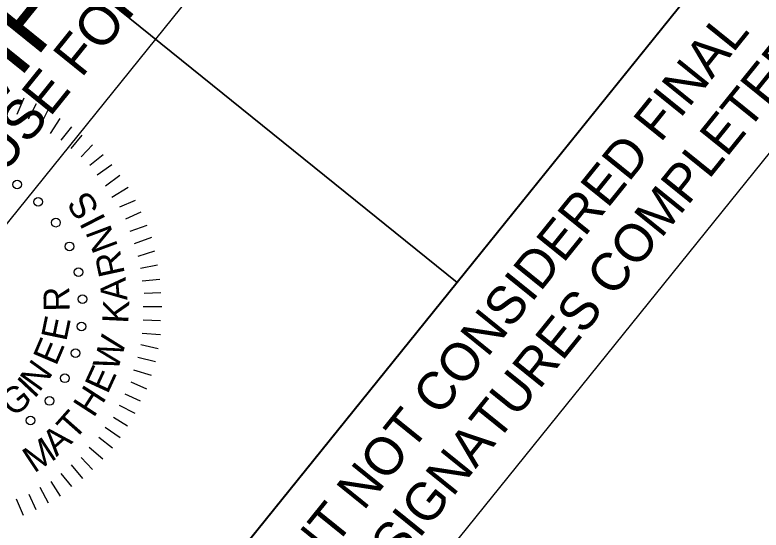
# Model space of a CAD drawing. Extents: x 1487832 to 1490056, y 498345 to 500343.
# Drawn here: x 1488928.7 to 1489037, y 500107.8 to 500182.6 of the extents above; entities that cross this region are included whole.
import ezdxf

# ---------------------------------------------------------------- set-up
doc = ezdxf.new("R2010")
doc.units = 0
for name, color, linetype in [('Old_Level_9', 7, 'Continuous'), ('Sheet Clip Boundary CELL', 7, 'Continuous'), ('Sheet Plan CELL', 7, 'Continuous'), ('Sheet Sticker Exception Certification CELL', 7, 'Continuous'), ('Sheet Sticker Incomplete CELL', 7, 'Continuous')]:
    doc.layers.add(name, color=color, linetype=linetype)

msp = doc.modelspace()

# ---------------------------------------------------------------- linework, layer by layer
at = {"layer": 'Old_Level_9'}
for p, q in [((1488930.01, 500170.5), (1488928.98, 500168.11)), ((1488931.8, 500169.69), (1488930.62, 500167.43)), ((1488933.47, 500168.74), (1488932.35, 500166.55)), ((1488935.23, 500167.57), (1488933.83, 500165.36)), ((1488936.93, 500166.33), (1488935.36, 500164.39)), ((1488938.4, 500165.14), (1488936.83, 500163.19)), ((1488939.98, 500163.74), (1488938.31, 500162)), ((1488941.49, 500162.27), (1488939.59, 500160.72)), ((1488942.78, 500160.84), (1488940.66, 500159.34)), ((1488943.94, 500159.26), (1488941.83, 500157.75)), ((1488945.12, 500157.54), (1488942.79, 500156.08)), ((1488946.18, 500155.66), (1488943.86, 500154.7)), ((1488947, 500153.97), (1488944.76, 500152.95)), ((1488947.85, 500152), (1488945.38, 500151.17)), ((1488948.53, 500150.29), (1488946, 500149.38)), ((1488948.96, 500148.28), (1488946.55, 500147.52)), ((1488949.39, 500146.26), (1488946.95, 500145.79)), ((1488949.75, 500144.17), (1488947.15, 500143.96)), ((1488949.89, 500142.26), (1488947.48, 500142.15)), ((1488950.04, 500140.22), (1488947.33, 500140.21)), ((1488949.82, 500138.2), (1488947.33, 500138.29)), ((1488949.83, 500136.14), (1488947.18, 500136.35)), ((1488949.48, 500134.11), (1488947, 500134.7)), ((1488949.11, 500132.22), (1488946.56, 500132.87)), ((1488948.54, 500130.24), (1488945.97, 500131.03)), ((1488947.83, 500128.25), (1488945.59, 500129.28)), ((1488946.95, 500126.52), (1488944.71, 500127.55)), ((1488946.15, 500124.72), (1488943.89, 500125.9)), ((1488945.06, 500122.9), (1488943.01, 500124.17)), ((1488943.96, 500121.22), (1488941.81, 500122.69)), ((1488942.85, 500119.68), (1488940.9, 500121.24)), ((1488941.45, 500118.1), (1488939.49, 500119.81)), ((1488939.98, 500116.59), (1488938.3, 500118.33)), ((1488938.55, 500115.3), (1488936.92, 500117.26)), ((1488936.97, 500114.14), (1488935.42, 500116.03)), ((1488935.34, 500112.75), (1488933.97, 500114.88)), ((1488933.6, 500111.72), (1488932.36, 500114)), ((1488931.79, 500110.74), (1488930.77, 500112.98)), ((1488929.96, 500109.9), (1488928.92, 500112.28))]:
    msp.add_line(p, q, dxfattribs=at)
for centre in [(1488929.02, 500157.96), (1488932.09, 500155.46), (1488934.66, 500152.43), (1488936.62, 500148.99), (1488937.92, 500145.24), (1488938.51, 500141.32), (1488938.37, 500137.36), (1488937.5, 500133.49), (1488935.94, 500129.84), (1488933.73, 500126.55), (1488930.96, 500123.72)]:
    msp.add_circle(centre, 0.63, dxfattribs=at)
at = {"layer": 'Sheet Clip Boundary CELL'}
msp.add_lwpolyline([(1488948.36, 500051.16), (1488813.25, 500160.1), (1488087.84, 499260.53), (1488879.09, 498569.08), (1489756.18, 499656.68), (1489073.94, 500206.87)], close=True, dxfattribs=at)
at = {"layer": 'Sheet Plan CELL'}
msp.add_line((1488905.31, 500214.39), (1488992.86, 500143.81), dxfattribs=at)
for points in [[(1488905.31, 500214.39), (1488968.07, 500292.23), (1489055.66, 500221.61), (1488992.89, 500143.76)], [(1488814.55, 498489.05), (1487997.21, 499148.15), (1488813.25, 500160.1), (1488930.07, 500065.91), (1489055.66, 500221.61), (1489756.18, 499656.68)], [(1488842.5, 500136.51), (1488905.31, 500214.39), (1488992.89, 500143.76), (1488930.07, 500065.91)]]:
    msp.add_lwpolyline(points, close=True, dxfattribs=at)
at = {"layer": 'Sheet Sticker Exception Certification CELL'}
for p, q in [((1488930.07, 500065.91), (1489055.65, 500221.62)), ((1488930.07, 500065.91), (1489055.65, 500221.62)), ((1489073.94, 500206.87), (1488948.36, 500051.16)), ((1489073.94, 500206.87), (1488948.36, 500051.16))]:
    msp.add_line(p, q, dxfattribs=at)
at = {"layer": 'Sheet Sticker Incomplete CELL'}
msp.add_lwpolyline([(1488902.95, 500121.87), (1488884.66, 500136.62), (1488976.94, 500251.05), (1488995.23, 500236.3)], close=True, dxfattribs=at)

# ---------------------------------------------------------------- texts
at = {"layer": 'Old_Level_9'}
for s, height, rotation, p in [('S', 3.78, 123.3735, (1488941.09, 500154.47)), ('I', 3.78, 117.162, (1488941.97, 500152.86)), ('N', 3.78, 110.4882, (1488943.71, 500148.98)), ('R', 3.78, 102.266, (1488944.69, 500145.03)), ('A', 3.78, 94.6373, (1488945.04, 500141.2)), ('R', 3.76, 91.4649, (1488936.66, 500139.56)), ('K', 3.78, 87.2567, (1488945.15, 500137.73)), ('E', 3.76, 78.2725, (1488936.15, 500135.1)), ('E', 3.76, 66.9213, (1488934.68, 500131.53)), ('W', 3.78, 73.1214, (1488943.56, 500130.72)), ('N', 3.76, 54.2434, (1488932.24, 500127.71)), ('E', 3.78, 65.2804, (1488942.14, 500127.43)), ('I', 3.76, 46.7402, (1488931.49, 500126.78)), ('G', 3.76, 38.5969, (1488928.44, 500124.1)), ('H', 3.78, 57.1269, (1488940.12, 500124)), ('T', 3.78, 48.5022, (1488937.3, 500120.68)), ('A', 3.78, 41.2978, (1488934.72, 500118.38)), ('M', 3.78, 33.4527, (1488931.48, 500116))]:
    msp.add_text(s, height=height, rotation=rotation, dxfattribs=at).set_placement(p)
at = {"layer": 'Sheet Sticker Exception Certification CELL'}
for s, p in [('DOCUMENT NOT CONSIDERED FINAL', (1488951.35, 500075.82)), ('DOCUMENT NOT CONSIDERED FINAL', (1488951.35, 500075.82)), ('UNLESS ALL SIGNATURES COMPLETED', (1488955.02, 500066.35)), ('UNLESS ALL SIGNATURES COMPLETED', (1488955.02, 500066.35))]:
    msp.add_text(s, height=5.5, rotation=51.1156, dxfattribs=at).set_placement(p)
at = {"layer": 'Sheet Sticker Incomplete CELL'}
for s, height, p in [('INCOMPLETE PLANS', 11.52, (1488899.47, 500136.18)), ('DO NOT USE FOR R/W ACQUISITION', 5.76, (1488906.92, 500134.35))]:
    msp.add_text(s, height=height, rotation=51.1156, dxfattribs=at).set_placement(p)

doc.saveas('drawing.dxf')
